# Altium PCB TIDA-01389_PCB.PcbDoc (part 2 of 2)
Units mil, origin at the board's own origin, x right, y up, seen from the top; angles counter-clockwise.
Board outline 3030.03 x 3369.98 mil, 2 copper layers (Top Layer, Bottom Layer), stack 62 mil thick; 50 components, 45 nets, 172 pads, 343 vias.
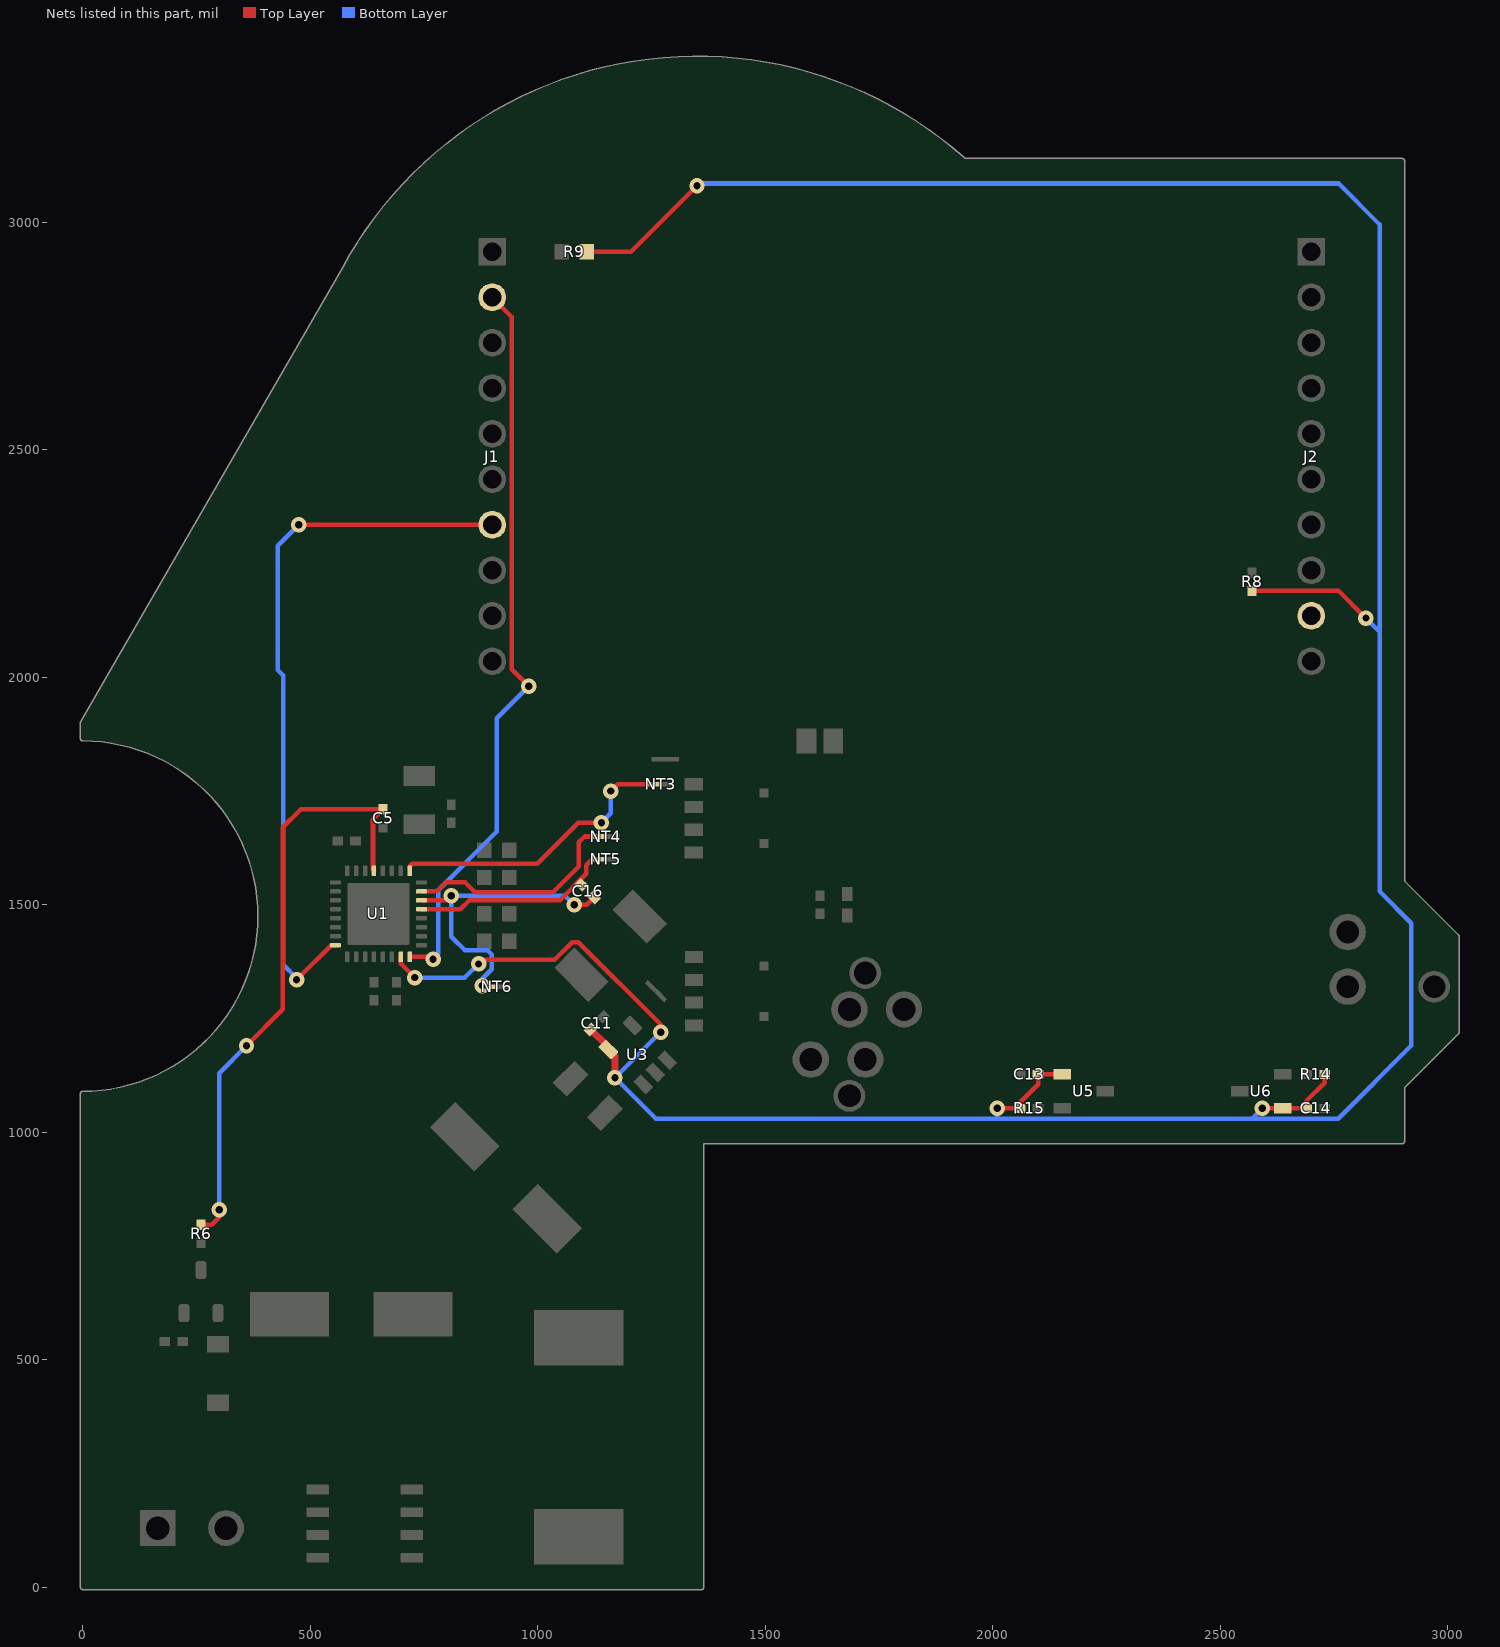
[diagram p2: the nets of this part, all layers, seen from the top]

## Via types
v1: diameter 30, hole 12, Top Layer to Bottom Layer, tented both sides, 267 vias
v2: diameter 34, hole 16, Top Layer to Bottom Layer, 39 vias
v3: diameter 30, hole 10, Top Layer to Bottom Layer, tented both sides, 32 vias
v4: diameter 19.68, hole 7.87, Top Layer to Bottom Layer, 5 vias

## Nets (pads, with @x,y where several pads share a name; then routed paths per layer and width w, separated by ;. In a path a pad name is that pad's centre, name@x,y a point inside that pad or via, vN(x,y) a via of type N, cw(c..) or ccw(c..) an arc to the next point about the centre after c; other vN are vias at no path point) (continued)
SH2: NT3.2 U1.25 | length 649.9
  Top Layer w10: U1.25@718.9,1574.49 718.9,1584.86 724.04,1590 998.99,1590 1088.99,1680 v2(1140,1680) ; v2(1160.77,1749.95) 1175.82,1765 NT3.2@1255,1765
  Bottom Layer w10: v2(1140,1680) 1160.77,1700.77 v2(1160.77,1749.95)
SL2: NT4.2 U1.23 | length 489.8
  Top Layer w10: U1.23@744.49,1529.21 778.2,1529.21 797.99,1549 841,1549 863,1527 1032.96,1527 1090,1584.04 1090,1637.01 1102.99,1650 NT4.2@1135,1650
SLEEP: J1.7 U1.8 | length 1578.1
  Top Layer w10: v2(470,1335) 546.1,1411.1 U1.8@555.51,1411.1 ; v2(475,2335) J1.7@900,2335
  Bottom Layer w10: v2(470,1335) 470,1338.99 441,1367.99 441,2003.95 429,2015.95 429,2289 v2(475,2335)
SN: C16.2 NT6.2 U1.22 | length 670.8
  Top Layer w10: U1.22@744.49,1509.53 799.53,1509.53 v2(810,1520) ; v2(1080,1500) 1107.84,1500 C16.2@1123.87,1516.04
  Bottom Layer w10: v2(878.28,1322.35) 878.28,1337.27 899,1357.99 899,1390.65 889.69,1399.95 840.05,1399.95 810,1430 v2(810,1520) 1060,1520 v2(1080,1500)
SO: J1.2 U1.16 | length 1642.7
  Top Layer w10: U1.16@718.9,1385.51 764.49,1385.51 v2(770,1380) ; J1.2@910,2825 J1.2@900,2835 942.51,2792.49 942.51,2017.39 942.61,2017.39 v2(980,1980)
  Bottom Layer w10: v2(770,1380) 781,1391 781,1532.01 910,1661.01 910,1910 v2(980,1980)
SP: C16.1 NT5.2 U1.21 | length 447.3
  Top Layer w10: U1.21@744.49,1489.84 829.84,1489.84 850,1510 1048.99,1510 1107,1568.01 1107,1587 1120,1600 NT5.2@1135,1600
UP: J2.9
VCC: C11.1 C13.1 C14.1 R8.2 R9.2 R14.2 R15.2 U1.15 U3.5 U5.1 U6.1 | length 7270.3
  Top Layer w10: U1.15@699.21,1385.51 699.21,1370.79 v2(730,1340) ; v2(870,1370) 879,1379 1036.86,1379 1075.69,1417.82 1089.11,1417.82 1270.22,1236.71 v2(1270.22,1220) ; R9.2@1107.56,2935 1205,2935 v2(1350,3080) ; U3.5@1155.27,1181.83 U3.5@1155.27,1186.89 ; v2(2010,1052.6) R15.2@2060.32,1052.6 2060.32,1066.06 2099.68,1105.43 C13.1@2099.68,1127.4 U5.1@2152.76,1127.4 ; R8.2@2570,2190.32 2759.7,2190.32 v2(2820.02,2130) ; v2(2592.33,1052.6) U6.1@2637.24,1052.6 C14.1@2690.32,1052.6 2690.31,1069.69 2729.68,1109.06 R14.2@2729.68,1127.4
  Top Layer w15: C11.1@1116.08,1226.08 U3.5@1155.27,1186.89 ; U3.5@1155.27,1181.83 1169.78,1167.33 v2(1169.78,1120)
  Bottom Layer w10: v2(730,1340) 840,1340 v2(870,1370) ; v2@1270,1220.22 v2(1169.78,1120) 1259.8,1029.98 2010,1029.98 ; v2@1355.02,3085.02 2760,3085.02 2850.02,2995 2850.02,2100 ; v2(2010,1052.6) 2010,1029.98 ; v2(2592.33,1052.6) 2569.71,1029.98 ; v2(2820.02,2130) 2850.02,2100 ; 2010,1029.98 2569.71,1029.98 ; 2569.71,1029.98 2759.3,1029.98 2920,1190.69 2920,1459.31 2850.02,1529.3 2850.02,2100
VCP: C5.2 R6.2 U1.29 | length 1343.2
  Top Layer w10: R6.2@260,796.68 283.32,796.68 300,813.37 v2(300,830) ; v2(360,1190) 440,1270 440,1670 479.68,1709.68 C5.2@660,1709.68 638,1687.68 638,1576.65 U1.29@640.16,1574.49
  Bottom Layer w10: v2(300,830) 300,1130 v2(360,1190)
pads on no net: J1.8 J2.2 J2.4 J2.5 U1. U1.9 U1.32

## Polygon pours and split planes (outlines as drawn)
GND on Top Layer "Top Layer-No Net 6" (solid, remove dead copper, pour order 55): 0,0 3100,0 3100,3400 0,3400 0,0
+V_BAT on Top Layer "+V_BAT_J4" (solid, remove dead copper, pour order 16): 243.53,-7.79 240,-4.26 240,440 560,440 560,0 251.32,0 243.53,-7.79
+V_SWITCH on Top Layer "Top Layer-No Net" (solid, remove dead copper, pour order 20): 640,0 640,650 900,650 900,300 1360,300 1360,-5.02 644.98,-5.02 640,-10
PVDD on Top Layer "Top Layer-No Net 1" (solid, remove dead copper, pour order 24): 1222.7,1126.21 900,803.52 900,800 900,300 1370,300 1370,970 1365.02,974.98 1380.03,990 1580,990 1580,1297.32 1580.98,1298.31 1579.29,1300 1400,1300 1400,1210 1410,1200 1400,1210 1300,1210 1300,1209.66 1199.92,1109.57
NetC17_1 on Top Layer "Top Layer-No Net 2" (solid, remove dead copper, pour order 28): 1430,1470 1430,1200 2000,1200 2000,1400 2000,1470 1430,1470
NetC17_2 on Top Layer "Top Layer-No Net 3" (solid, remove dead copper, pour order 30): 1425,1698.46 1425,1535 1430,1530 2500,1530 2600,1530 2700,1430 2700,1200 2900,1200 2910,1210 2910,1580 2790,1700 1426.54,1700
NetNT4_1 on Top Layer "Top Layer-No Net 4" (solid, remove dead copper, pour order 39): 1240.73,1410 1240.73,1409.27 1255.86,1394.14 1338.28,1360 1400,1360 1400,1680 1160,1680 1160,1490
PVDD on Top Layer "Top Layer-No Net 5" (solid, remove dead copper, pour order 45): 1300,1960 1300,1700 1301.54,1698.46 1606.4,1698.46 1606.4,1953.6 1600,1960 1300,1960
PVDD on Bottom Layer "Bottom Layer-No Net" (solid, remove dead copper, pour order 43): 1300,1000 1600,1000 1600,1950 1590,1960 1300,1960 1300,1010
GND on Bottom Layer "Bottom Layer-No Net 1" (solid, remove dead copper, pour order 53): 0,-10.02 9.98,-20 3110,-20 3110,3400 3070,3440 0,3440 0,0

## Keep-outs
Keep-Out Layer:
  lines w10: -10.02,0.13 -10.02,0.19 ; -10.02,0.19 ccw(c0,0) 0,-10.02 ccw(c0,-5.02) 0.13,-10.02 1360,-10.02 ccw(c1360,0) 1370.02,0 1370.02,969.98 2900,969.98 ccw(c2900,980) 2910.02,980 2910.02,1095.85 3027.05,1212.88 ; -10.02,0.19 -10.02,1085 cw(c0,1085) 0,1095.02 ccw(c0,1475) 379.98,1475 ccw(c0,1475) 0,1854.98 cw(c0,1865) -10.02,1865 -10.02,1900 cw(c0,1900) -8.68,1905 cw(c-4.34,1902.51) -8.67,1905.01 ; -8.67,1905.01 ccw(c-4.34,1902.51) -8.67,1905.01 ; -8.67,1905.02 ccw(c-4.34,1902.51) -8.67,1905.01 ; -8.67,1905.01 ccw(c-4.34,1902.51) -8.67,1905.01 ; -8.67,1905.01 -8.67,1905.02 ; -8.67,1905.02 -8.67,1905.02 ; -8.67,1905.01 -8.67,1905.01 ; -8.67,1905.01 -8.67,1905.02 ; -8.67,1905.02 566.76,2902.69 cw(c1350,2480) 1940.03,3146.33 cw(c1933.39,3138.83) 1940.47,3145.91 ; 1940.47,3145.91 cw(c1933.39,3138.83) 1940.49,3145.89 ; 1940.47,3145.91 1940.49,3145.89 ; 1940.47,3145.91 1940.51,3145.88 ; 1940.51,3145.88 ccw(c1933.39,3138.83) 1940.49,3145.89 ; 1940.51,3145.88 ccw(c1936.95,3142.36) 1940.51,3145.88 ; 1940.51,3145.88 ccw(c1936.95,3142.36) 1940.49,3145.89 ; 1940.51,3145.88 1941.37,3145.02 2900,3145.02 cw(c2900,3135) 2910.02,3135 2910.02,1554.15 3027.05,1437.12 ; 3027.05,1212.88 ccw(c3023.53,1216.44) 3027.07,1212.9 ; 3027.05,1212.88 ccw(c3023.53,1216.44) 3027.05,1212.88 ; 3027.05,1212.88 ccw(c3020,1220) 3027.07,1212.9 ; 3027.07,1212.9 ccw(c3020,1220) 3027.08,1212.92 ; 3027.05,1212.88 3027.08,1212.92 ; 3027.07,1212.9 3027.08,1212.92 ; 3027.07,1437.1 cw(c3020,1430) 3027.08,1437.08 ; 3027.07,1437.1 ccw(c3020,1430) 3027.05,1437.12 ; 3027.05,1437.12 ccw(c3023.53,1433.56) 3027.05,1437.12 ; 3027.07,1437.1 ccw(c3023.53,1433.56) 3027.05,1437.12 ; 3027.05,1437.12 3027.08,1437.08 ; 3027.07,1437.1 3027.08,1437.08 ; 3027.08,1212.92 ccw(c3020,1220) 3030.02,1220 3030.02,1430 ccw(c3020,1430) 3027.08,1437.08
  text ".Layer_Name" at 577,-858.49 h60

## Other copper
Top Layer:
  text ".Layer_Name" at 577,-858.49 h60
Bottom Layer:
  text ".Layer_Name" at 577,-858.49 h60

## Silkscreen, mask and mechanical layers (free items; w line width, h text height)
Top Overlay:
  lines w5: 440.05,1260.05 440.05,1860.05 900,1860 910,1860 910,1260 440.05,1260.05 ; 1980,1000 2800,1000 2800,1200 1980,1200 1980,1000
  text ".PRJ_Number" at 2120,1530 h60
  text ".PCB_Rev" at 2450,1530 h60
  text "DRV5013-Q1" at 2210,1210 h60
  text "DRV8703-Q1" at 530,1200 h60
  text ".Layer_Name" at 577,-858.49 h60
Bottom Overlay:
  text ".Layer_Name" at 577,-858.49 h60
Top Paste:
  text ".Layer_Name" at 577,-858.49 h60
Bottom Paste:
  text ".Layer_Name" at 577,-858.49 h60
Top Solder:
  text ".Layer_Name" at 577,-858.49 h60
  text ".Layer_Name" at 577,-858.49 h60
Bottom Solder:
  text ".Layer_Name" at 577,-858.49 h60
Drill Guide:
  text ".Layer_Name" at 577,-858.49 h60
M1 Board Outline:
  circle w10: c1350,2480 r195
  circle w10: c1950,1505 r100
  lines w10: 0,0 ccw(c0,0) 0,0 ; 0,0 0,1085 ccw(c0,1475) 0,1865 0,1900 575.51,2897.81 cw(c1350,2480) 1933.39,3138.83 1937.22,3135 2900,3135 2900,1550 3020,1430 3020,1220 2900,1100 2900,980 1360,980 1360,0 0,0
  text ".Layer_Name" at 577,-858.49 h60
M2 Board Dimensions:
  rectangle: 125,-400 500,-275
  rectangle: 0,-275 125,-150
  lines w7: 0,-275 1000,-275 ; 0,-150 0,-400 1000,-400 1000,-150 ; 125,-400 125,-150 ; 250,-400 250,-150 ; 500,-400 500,-150 ; 750,-400 750,-150
  text ".Layer_Name" at 577,-858.49 h60
M3 3D STEP Top:
  text ".Layer_Name" at 577,-858.49 h60
M4 3D STEP Bottom:
  text ".Layer_Name" at 577,-858.49 h60
M5 Assembly Top:
  lines w10: -292,-930.17 6308,-930.17 ; -292,-726.83 6310,-726.83 ; -292,-523.5 -292,-1133.5 3713,-1133.5 6310,-1133.5 6310,-523.5 -291.5,-523.5 -291.5,-1133.5 1284,-1133.5 ; 2173,-1133.5 2173,-523.5 ; 3440,-726.83 3440,-523.5 ; 4280,-726.83 4280,-523.5 ; 4902,-1140 4902,-937.17
  text "COMPONENTS MARKED 'DNP' SHOULD NOT BE POPULATED." at 1153.5,-318.5 h60
  text "ASSEMBLY VARIANT:" at 1153,-434 h60
  text ".VariantName" at 2189,-434 h60
  text "PCB VIEWED FROM TOP SIDE" at -228.5,-655.67 h60
  text "BOARD #:" at 2248,-655.67 h60
  text ".PRJ_Number" at 2793.5,-655.67 h60
  text "REV:" at 3638,-655.67 h60
  text ".PCB_Rev" at 3929.5,-655.67 h60
  text "SVN REV:" at 4476,-655.67 h60
  text ".VersionControl_RevNumber" at 4982,-655.67 h60
  text "TID #:" at 2248,-859 h60
  text ".TID" at 2793.5,-859 h60
  text "PLOT NAME =" at -228.5,-1064.34 h60
  text ".plot_File_Name" at 577,-1064.34 h60
  text "GENERATED    :" at 2250,-1064.34 h60
  text ".Print_Date" at 3119.5,-1064.34 h60
  text ".Print_Time" at 3848.5,-1064.34 h60
  text "TEXAS INSTRUMENTS" at 5113,-1064.34 h60
M6 Assembly Bottom:
  lines w10: -292.5,-727.33 6309.5,-727.33 ; -290.5,-930.67 6309.5,-930.67 ; 1115.5,-1140.5 1115.5,-937.67 ; 1737.5,-727.33 1737.5,-524 ; 2577.5,-727.33 2577.5,-524 ; 3844.5,-1134 3844.5,-524 ; 4733.5,-1134 6309,-1134 6309,-524 -292.5,-524 -292.5,-1134 2304.5,-1134 6309.5,-1134 6309.5,-524
  text "COMPONENTS MARKED 'DNP' SHOULD NOT BE POPULATED." at 6102,-318 h60
  text ".VariantName" at 5058,-434 h60
  text "ASSEMBLY VARIANT:" at 6097,-434 h60
  text ".VersionControl_RevNumber" at 1035.5,-656.17 h60
  text "SVN REV:" at 1541.5,-656.17 h60
  text ".PCB_Rev" at 2088,-656.17 h60
  text "REV:" at 2379.5,-656.17 h60
  text ".PRJ_Number" at 3224,-656.17 h60
  text "BOARD #:" at 3769.5,-656.17 h60
  text "PCB VIEWED FROM BOTTOM SIDE" at 6246,-656.17 h60
  text ".TID" at 3224,-859.5 h60
  text "TID #:" at 3769.5,-859.5 h60
  text "TEXAS INSTRUMENTS" at 904.5,-1064.84 h60
  text ".Print_Time" at 2169,-1064.84 h60
  text ".Print_Date" at 2898,-1064.84 h60
  text "GENERATED    :" at 3767.5,-1064.84 h60
  text ".plot_File_Name" at 5440.5,-1064.84 h60
  text "PLOT NAME =" at 6246,-1064.84 h60
M9 Title Sheet:
  drawing of 57 lines, arcs and shapes, not listed
  text "1" at 739.84,8036.5 h70
  text "2" at 3235.5,8036.5 h70
  text "3" at 5724.84,8036.5 h70
  text "4" at 8231.51,8036.5 h70
  text "5" at 10730.5,8036.5 h70
  text "6" at 13235.5,8036.5 h70
  text "A" at -416.5,6893.5 h70
  text "A" at 14383.5,6893.5 h70
  text "B" at -416.5,4513.5 h70
  text "B" at 14383.5,4513.5 h70
  text "C" at -416.5,2138.5 h70
  text "C" at 14383.5,2138.5 h70
  text "PROJECT TITLE:" at 11343.5,277.5 h45
  text ".PRJ_Title" at 11393.5,144.17 h70
  text "DESIGNED FOR:" at 11343.5,-23.5 h45
  text ".PRJ_Customer" at 11393.5,-163.5 h70
  text "D" at -416.5,-231.5 h70
  text "D" at 14383.5,-231.5 h70
  text "FILE NAME:" at 11343.5,-323.5 h45
  text ".PCB_File_Name_No_Path" at 11393.5,-443.5 h70
  text "Texas Instruments (TI) and/or its licensors do not warrant the accuracy or completeness of this specification" at 6374,-605.34 h45
  text "ENGINEER:" at 11343.5,-613.5 h45
  text "LAYOUT BY:" at 12848.5,-613.5 h45
  text "or any information contained therein. TI and/or its licensors do not warrant that this design will meet" at 6329.01,-718 h45
  text ".PRJ_Engineer" at 11393.5,-768.49 h70
  text ".PCB_Layout" at 12899,-768.49 h70
  text "the specifications, will be suitable for your application or fit for any particular purpose, or will operate in" at 6329.01,-830.67 h45
  text ".Layer_Name" at 577,-858.49 h60
  text "ALTIUM DESIGNER VERSION:" at 12848.5,-923.5 h45
  text "an implementation. TI and/or its licensors do not warrant that the design is production worthy. You should" at 6329.01,-943.33 h45
  text "completely validate and test your design implementation to confirm the system functionality for your application." at 6374,-1056 h45
  text ".print_Scale" at 11393.5,-1056.83 h70
  text ".Application_BuildNumber" at 12899,-1056.83 h70
  text "1" at 739.84,-1263.5 h70
  text "2" at 3235.5,-1263.5 h70
  text "3" at 5724.84,-1263.5 h70
  text "4" at 8231.51,-1263.5 h70
  text "5" at 10730.5,-1263.5 h70
  text "6" at 13235.5,-1263.5 h70
M10 Fab Notes:
  drawing of 173 lines, arcs and shapes, not listed
  text "DESIGN INFORMATION" at 12377.02,6201 h60
  text "MIN. TRACK WIDTH:" at 11732.46,6021 h60
  text "8" at 12828.7,6021 h60
  text "MIL" at 12983.46,6021 h60
  text "MIN. CLEARANCE:" at 11732.46,5889 h60
  text "0.2" at 12768.7,5889 h60
  text "mm" at 12983.46,5889 h60
  text "MIN. VIA PAD SIZE:" at 11732.46,5757 h60
  text "24" at 12798.71,5757 h60
  text "MIL" at 12983.46,5757 h60
  text "0.05mm (2MIL)" at 12427.46,5615.29 h60
  text "MINIMUM ANNULAR RING" at 11403.23,5611 h60
  text "EXTERNAL" at 13135.46,5611 h60
  text "PER" at 11603.23,5493 h60
  text "IPC-D-275 CLASS 2 LEVEL C" at 11823.23,5493 h60
  text "MIL, HOLES" at 13311.46,5380.71 h60
  text "+/-" at 12919,5380 h60
  text "+/-" at 13773,5380 h60
  text "REGISTRATION TOLERANCES:" at 11403.23,5375 h60
  text "METAL" at 12603,5375 h60
  text "5" at 13179.2,5375 h60
  text "3" at 14012.2,5375 h60
  text "MIL" at 14128.46,5375 h60
  text "+/-" at 13773,5262 h60
  text "HOLE SIZE TOLERANCE (UNLESS OTHERWISE SPECIFIED):" at 11403.23,5257 h60
  text "3" at 14012.2,5257 h60
  text "MIL" at 14128.46,5257 h60
  text "MATERIAL:" at 11328.46,5047.54 h60
  text "FR-4 High Tg" at 12314.9,4907.21 h60
  text "FR-408" at 11749.46,4898.64 h60
  text "OTHER" at 13237.46,4898.64 h60
  text "X" at 12160,4895 h60
  text "62 MIL (1.6mm) +/-10%" at 12069.56,4735.92 h60
  text "THICKNESS:" at 11403.23,4731.64 h60
  text "X" at 11941.4,4731.64 h60
  text "OTHER" at 13354.46,4731.64 h60
  text "TOLERANCE:" at 11403.23,4573.64 h60
  text "X" at 12242.53,4573.64 h60
  text "ANSI IPC-6012 TYPE 3 CLASS 2" at 12429.48,4573.64 h60
  text "OTHER +/-" at 12429.46,4417.64 h60
  text "BOW & TWIST:" at 11403.23,4260.64 h60
  text "X" at 12242.53,4260.64 h60
  text "ANSI IPC-6012 TYPE 3 CLASS 2" at 12429.48,4260.64 h60
  text "OTHER +/-" at 12429.46,4102.13 h60
  text "DRILLING:" at 11328.46,3963.64 h60
  text "REFERENCE:" at 11403.23,3846.64 h60
  text "X" at 12051.46,3846.64 h60
  text "AS SHOWN" at 12238.46,3846.64 h60
  text "X" at 12952.46,3846.64 h60
  text "NC_DRILL FILES" at 13089.46,3846.64 h60
  text "PTH COPPER THICKNESS:" at 11403.23,3688.64 h60
  text "X" at 12533.46,3688.64 h60
  text "20-30 um" at 12670.46,3688.64 h60
  text "OTHER" at 13387.46,3688.64 h60
  text "BOARD FINISH:" at 11328.46,3529.64 h60
  text "SILKSCREEN:" at 11483.68,3411.64 h60
  text "X" at 12432.46,3411.64 h60
  text "TOP" at 12558.46,3411.64 h60
  text "X" at 12942.46,3411.64 h60
  text "BOTTOM" at 13069.46,3411.64 h60
  text "SILKSCREEN COLOR:" at 11483.68,3244.64 h60
  text "X" at 12431.42,3244.64 h60
  text "WHITE" at 12558.46,3244.64 h60
  text "OTHER" at 13069.46,3244.64 h60
  text "X" at 12562.42,3085.44 h60
  text "GREEN" at 12689.46,3085.44 h60
  text "OTHER" at 13307.46,3085.44 h60
  text "SOLDER RESIST COLOR:" at 11483.68,3074.64 h60
  text "X" at 12562.42,2915.44 h60
  text "MATTE" at 12689.46,2915.44 h60
  text "SEMI-GLOSS" at 13307,2914.8 h60
  text "IMMERSION GOLD (ENIG)" at 12389.46,2726.92 h60
  text "ENEPIG" at 13727,2723.64 h60
  text "SURFACE FINISH:" at 11328.46,2722.64 h60
  text "X" at 12202.51,2722.64 h60
  text "IMM. TIN/SILVER OR EQUIV" at 11658,2565.64 h60
  text "OTHER" at 13089.46,2565.64 h60
  text "ARRAY/PANEL:" at 11328.46,2386.64 h60
  text "CUT AND TRIM PER M1 BOARD OUTLINE" at 12389.46,2382.35 h60
  text "N.C. ROUTE" at 12389.46,2230.64 h60
  text "X" at 13068.46,2230.64 h60
  text "V. SCORE" at 13255.46,2230.64 h60
  text "CERTIFICATION:" at 11328.46,2093.64 h60
  text "MATERIALS AND WORKMANSHIP FOR ALL PCBS" at 12053.46,2093.64 h60
  text "TO MEET OR EXCEED THE REQUIREMENTS OF:" at 12053.46,1995.64 h60
  text "X" at 11679.96,1859.13 h60
  text "ANSI IPC-A-600F CLASS ->" at 11818.96,1859.13 h60
  text "X" at 13458.02,1859.13 h60
  text "2" at 13576.96,1859.14 h60
  text "1" at 13261.96,1857.64 h60
  text "3" at 13930.96,1857.64 h60
  text "X" at 12494.02,1699.64 h60
  text "RoHS" at 12630.96,1699.64 h60
  text "OTHER" at 13275.36,1699.64 h60
  text "PER ORDER" at 13672.42,1699.64 h60
  text "ALL BOARDS MUST MEET OR EXCEED UL94-V0 REQUIREMENTS." at 11356,1534 h60
  text "PCB MUST BEAR THE UL94V-0 UL REGISTERED MATERIAL ID NUMBER" at 11356,1414 h60
  text "ADDITIONAL REQUIREMENTS:" at 11328.46,1240.64 h60
  text "MICROSECTION:" at 11403.23,1125.64 h60
  text "YES" at 12308.96,1125.64 h60
  text "REQUIRED" at 13170.46,969.49 h60
  text "BARE BOARD ELEC. TEST:" at 11403.23,966.64 h60
  text "NONE" at 12708.96,966.64 h60
  text "X" at 13043.46,966.64 h60
  text "PER ORDER" at 13762.46,966.64 h60
  text ".Layer_Name" at 577,-858.49 h60
M11 Gerber Information:
  lines w10: -292,-930.17 6308,-930.17 ; -292,-726.83 6310,-726.83 ; -292,-523.5 -292,-1133.5 3713,-1133.5 6310,-1133.5 6310,-523.5 -291.5,-523.5 -291.5,-1133.5 1284,-1133.5 ; 2173,-1133.5 2173,-523.5 ; 3440,-726.83 3440,-523.5 ; 4280,-726.83 4280,-523.5 ; 4902,-1140 4902,-937.17
  text "ALL ARTWORK VIEWED FROM TOP SIDE" at -228.5,-655.67 h60
  text "BOARD #:" at 2248,-655.67 h60
  text ".PRJ_Number" at 2793.5,-655.67 h60
  text "REV:" at 3638,-655.67 h60
  text ".PCB_Rev" at 3929.5,-655.67 h60
  text "SVN REV:" at 4476,-655.67 h60
  text ".VersionControl_RevNumber" at 4982,-655.67 h60
  text "LAYER NAME =" at -228.5,-858.49 h60
  text "TID #:" at 2248,-859 h60
  text ".TID" at 2793.5,-859 h60
  text "PLOT NAME =" at -228.5,-1064.34 h60
  text ".plot_File_Name" at 577,-1064.34 h60
  text "GENERATED    :" at 2250,-1064.34 h60
  text ".Print_Date" at 3119.5,-1064.34 h60
  text ".Print_Time" at 3848.5,-1064.34 h60
  text "TEXAS INSTRUMENTS" at 5113,-1064.34 h60
M12 Stackup:
  drawing of 191 lines, arcs and shapes, not listed
  text "Layer" at 9790.58,7830 h60
  text "Name" at 10200.49,7830 h60
  text "Material" at 11130.23,7830 h60
  text "Thickness" at 11990,7830 h60
  text "Constant" at 12639.84,7830 h60
  text "Board Layer Stack" at 13209.7,7830 h60
  text "1" at 9790.58,7710 h60
  text "Top Overlay" at 10200.49,7710 h60
  text "2" at 9790.58,7590 h60
  text "Top Solder" at 10200.49,7590 h60
  text "Solder Resist" at 11130.23,7590 h60
  text "0.40mil" at 11990,7590 h60
  text "3.5" at 12639.84,7590 h60
  text "3" at 9790.58,7470 h60
  text "Top Layer" at 10200.49,7470 h60
  text "Copper" at 11130.23,7470 h60
  text "1.40mil" at 11990,7470 h60
  text "4" at 9790.58,7350 h60
  text "Dielectric1" at 10200.49,7350 h60
  text "FR-4" at 11130.23,7350 h60
  text "59.20mil" at 11990,7350 h60
  text "4.8" at 12639.84,7350 h60
  text "5" at 9790.58,7230 h60
  text "Bottom Layer" at 10200.49,7230 h60
  text "Copper" at 11130.23,7230 h60
  text "1.40mil" at 11990,7230 h60
  text "6" at 9790.58,7110 h60
  text "Bottom Solder" at 10200.49,7110 h60
  text "Solder Resist" at 11130.23,7110 h60
  text "0.40mil" at 11990,7110 h60
  text "3.5" at 12639.84,7110 h60
  text "7" at 9790.58,6990 h60
  text "Bottom Overlay" at 10200.49,6990 h60
  text ".Layer_Name" at 577,-858.49 h60
M13 Component Bodies Top:
  text ".Layer_Name" at 577,-858.49 h60
M14 Component Bodies Bottom:
  text ".Layer_Name" at 577,-858.49 h60
M15 Courtyards Top:
  text ".Layer_Name" at 577,-858.49 h60
M16 Courtyards Bottom:
  text ".Layer_Name" at 577,-858.49 h60
Drill Drawing:
  circle w10: c5563.72,2769 r16.58
  circle w10: c5563.72,2769 r27.63
  lines w10: 5536.09,2492.74 5591.34,2492.74 5591.34,2547.99 5536.09,2547.99 5536.09,2492.74 ; 5536.09,2672.31 5591.34,2672.31 5563.72,2617.06 5536.09,2672.31 ; 5536.09,2865.7 5563.72,2879.51 5591.34,2865.7 5577.53,2893.32 5591.34,2920.95 5563.72,2907.14 5536.09,2920.95 5549.9,2893.32 5536.09,2865.7 ; 5536.09,3045.27 5591.34,3045.27 5563.72,2990.02 5536.09,3045.27 ; 5536.09,3114.34 5536.09,3128.15 5549.9,3141.96 5536.09,3155.78 5536.09,3169.59 5549.9,3169.59 5563.72,3155.78 5577.53,3169.59 5591.34,3169.59 5591.34,3155.78 5577.53,3141.96 5591.34,3128.15 5591.34,3114.34 5577.53,3114.34 5563.72,3128.15 5549.9,3114.34 5536.09,3114.34 ; 5536.09,3252.47 5549.9,3252.47 5563.72,3238.66 5577.53,3252.47 5591.34,3252.47 5577.53,3266.28 5591.34,3280.1 5577.53,3280.1 5563.72,3293.91 5549.9,3280.1 5536.09,3280.1 5549.9,3266.28 5536.09,3252.47 ; 5547.14,2503.79 5580.29,2503.79 5580.29,2536.94 5547.14,2536.94 5547.14,2503.79 ; 5547.14,2661.26 5580.29,2661.26 5563.72,2628.11 5547.14,2661.26 ; 5547.14,2876.75 5563.72,2885.03 5580.29,2876.75 5572.01,2893.32 5580.29,2909.9 5563.72,2901.61 5547.14,2909.9 5555.43,2893.32 5547.14,2876.75 ; 5547.14,3125.39 5547.14,3133.67 5555.43,3141.96 5547.14,3150.25 5547.14,3158.54 5555.43,3158.54 5563.72,3150.25 5572.01,3158.54 5580.29,3158.54 5580.29,3150.25 5572.01,3141.96 5580.29,3133.67 5580.29,3125.39 5572.01,3125.39 5563.72,3133.67 5555.43,3125.39 5547.14,3125.39 ; 5547.14,3257.99 5555.43,3257.99 5563.72,3249.71 5572.01,3257.99 5580.29,3257.99 5572.01,3266.28 5580.29,3274.57 5572.01,3274.57 5563.72,3282.86 5555.43,3274.57 5547.14,3274.57 5555.43,3266.28 5547.14,3257.99
  lines w12: 5486,2455.44 7464.02,2455.44 ; 5486,3325.68 7464.02,3325.68 ; 5823.86,2331.12 5823.86,3450 ; 6155.86,2331.12 6155.86,3450 ; 6792.43,2331.12 6792.43,3450 ; 7051.57,2331.12 7051.57,3450 ; 5486,2331.12 7464.02,2331.12 7464.02,3450 5486,3450 5486,2331.12
  text "Symbol" at 5560.59,3362.98 h72
  text "Quantity" at 5861.16,3362.98 h72
  text "Finished Hole Size" at 6193.16,3362.98 h72
  text "Plated" at 6829.72,3362.98 h72
  text "Hole Type" at 7088.86,3362.98 h72
  text "5" at 5861.16,3238.66 h60
  text "7.87mil (0.200mm)" at 6193.16,3238.66 h60
  text "PTH" at 6829.72,3238.66 h60
  text "Round" at 7088.86,3238.66 h60
  text "32" at 5861.16,3114.34 h60
  text "10.00mil (0.254mm)" at 6193.16,3114.34 h60
  text "PTH" at 6829.72,3114.34 h60
  text "Round" at 7088.86,3114.34 h60
  text "267" at 5861.16,2990.02 h60
  text "12.00mil (0.305mm)" at 6193.16,2990.02 h60
  text "PTH" at 6829.72,2990.02 h60
  text "Round" at 7088.86,2990.02 h60
  text "39" at 5861.16,2865.7 h60
  text "16.00mil (0.406mm)" at 6193.16,2865.7 h60
  text "PTH" at 6829.72,2865.7 h60
  text "Round" at 7088.86,2865.7 h60
  text "20" at 5861.16,2741.38 h60
  text "40.16mil (1.020mm)" at 6193.16,2741.38 h60
  text "PTH" at 6829.72,2741.38 h60
  text "Round" at 7088.86,2741.38 h60
  text "9" at 5861.16,2617.06 h60
  text "50.00mil (1.270mm)" at 6193.16,2617.06 h60
  text "PTH" at 6829.72,2617.06 h60
  text "Round" at 7088.86,2617.06 h60
  text "2" at 5861.16,2492.74 h60
  text "51.18mil (1.300mm)" at 6193.16,2492.74 h60
  text "PTH" at 6829.72,2492.74 h60
  text "Round" at 7088.86,2492.74 h60
  text "374 Total" at 5861.16,2368.42 h60
  text ".Layer_Name" at 577,-858.49 h60

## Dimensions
0,-400 to 1000,-400 on M2 Board Dimensions
0,0 to 1340,3370 on M2 Board Dimensions
0,0 to 3025.01,1220 on M2 Board Dimensions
